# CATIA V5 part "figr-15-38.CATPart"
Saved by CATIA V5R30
Part number: Part1
Bounding box of the stored display mesh (mm): x -63.331 to 69.186, y -39.139 to 39.139, z 0 to 69.963
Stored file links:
  D:\PROJECTS\CATIA V56R 2020\Resources\Parts File\c15_catia_v5_6r2020_prt\figr-15-38.CATPart
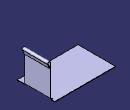
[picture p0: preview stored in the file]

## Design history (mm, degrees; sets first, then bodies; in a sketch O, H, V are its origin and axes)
SheetMetalParameters1: Thickness 1, BendRadius 2, KFactor 0.400515 {= log(min(100,max(20*SheetMetalParameters1.BendRadius,SheetMetalParameters1.Thickness)/SheetMetalParameters1.Thickness))/log(100)/2}, ReliefRadialLength 1, ReliefAxialLength 2, MinimumBendRadius 0
Body1 (main body)
  Sketch1 on xy-plane, origin (0, 0, 0), H (1, 0, 0), V (0, 1, 0)
    line L1 (-63.3311, 39.1393) -> (63.3311, 39.1393)
    line L2 (63.3311, 39.1393) -> (63.3311, -39.1393)
    line L3 (63.3311, -39.1393) -> (-63.3311, -39.1393)
    line L4 (-63.3311, -39.1393) -> (-63.3311, 39.1393)
    horizontal: L1 H, L3 H
    vertical: L2 V, L4 V
    symmetry: L4 L2 V, L1 L3 H
  Wall1: Thickness 1, Profile Sketch1
  d_NewWallOnEdge1: NewWallOnEdge_Edge edge [face of Wall1 | face of Wall1], NewWallOnEdge_Length 67, NewWallOnEdge_HeightLimitOffset 0, NewWallOnEdge_WidthOffset1 -16, NewWallOnEdge_WidthOffset2 -9, NewWallOnEdge_Angle 90, NewWallOnEdge_BendRadiusValue 2 {= SheetMetalParameters1.BendRadius}, NewWallOnEdge_BendTable SheetMetalParameters1, KFacteur 0.400515 {= log(min(100,max(20*d_NewWallOnEdge1.Radius,SheetMetalParameters1.Thickness)/SheetMetalParameters1.Thickness))/log(100)/2}
  Flange1: Angle 22.6199 {= 2*atan(Flange1.Radius/Flange1.Length)}, Length 10, Radius 2, KFacteur 0.400515 {= log(min(100,max(20*Flange1.Radius,SheetMetalParameters1.Thickness)/SheetMetalParameters1.Thickness))/log(100)/2}, Guide edge [face of d_NewWallOnEdge1 | face of d_NewWallOnEdge1]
